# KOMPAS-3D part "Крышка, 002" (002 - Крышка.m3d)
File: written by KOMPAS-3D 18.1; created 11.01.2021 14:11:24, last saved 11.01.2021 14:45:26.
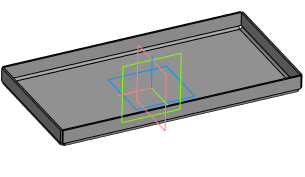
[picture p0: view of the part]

Document properties: Полное имя файла: D:\Ящик\002 - Крышка.m3d

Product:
- Part/product: Крышка  | designation 002
    Масса: 0.3497
    source file: Развертки.cdw

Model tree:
1. Эскиз:1
2. Листовое тело:1
     Расстояние 1 = 10; Радиус сгиба = 2
3. Сгиб:2  (with: Листовое тело:1)
     Радиус сгиба = 2; Коэффициент = 0.4; Величина сгиба = 10; Радиус сгиба = 2; Коэффициент = 0.4; Величина сгиба = 10; Радиус сгиба = 2; Коэффициент = 0.4; Величина сгиба = 10; Радиус сгиба = 2; Коэффициент = 0.4; Величина сгиба = 10; Толщина листового тела = 1.5; Ширина освобождения сгиба = 0.5; Ширина сгиба = 207; Длина 1 = 15; Длина 2 = 10
4. Развертка  (with: Листовое тело:1)

Expressions: L+2*T_met+2*R_gib; K+2*T_met+2*R_gib
Referenced files in D:\Ящик\: Сборка.a3d||L, Сборка.a3d||K, Сборка.a3d||T_met, Сборка.a3d||R_gib
Referenced files in D:\Временные файлы КОМПАСа\Ящик_мойки\: Сборка.a3d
